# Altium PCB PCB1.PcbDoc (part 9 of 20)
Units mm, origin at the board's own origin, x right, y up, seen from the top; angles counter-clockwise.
Board outline 294.51 x 138.18 mm, 12 copper layers (Top Layer 1 _Signal, L2_GND, L3_Signals, L4_GND, L5_POWER, L6_Signals, L7_GND, L8_Signals, L9_GND, L10_POWER, L11_GND, Bottom Layer_Signals), stack 1.788 mm thick; 1254 components, 836 nets, 5699 pads, 2073 vias.
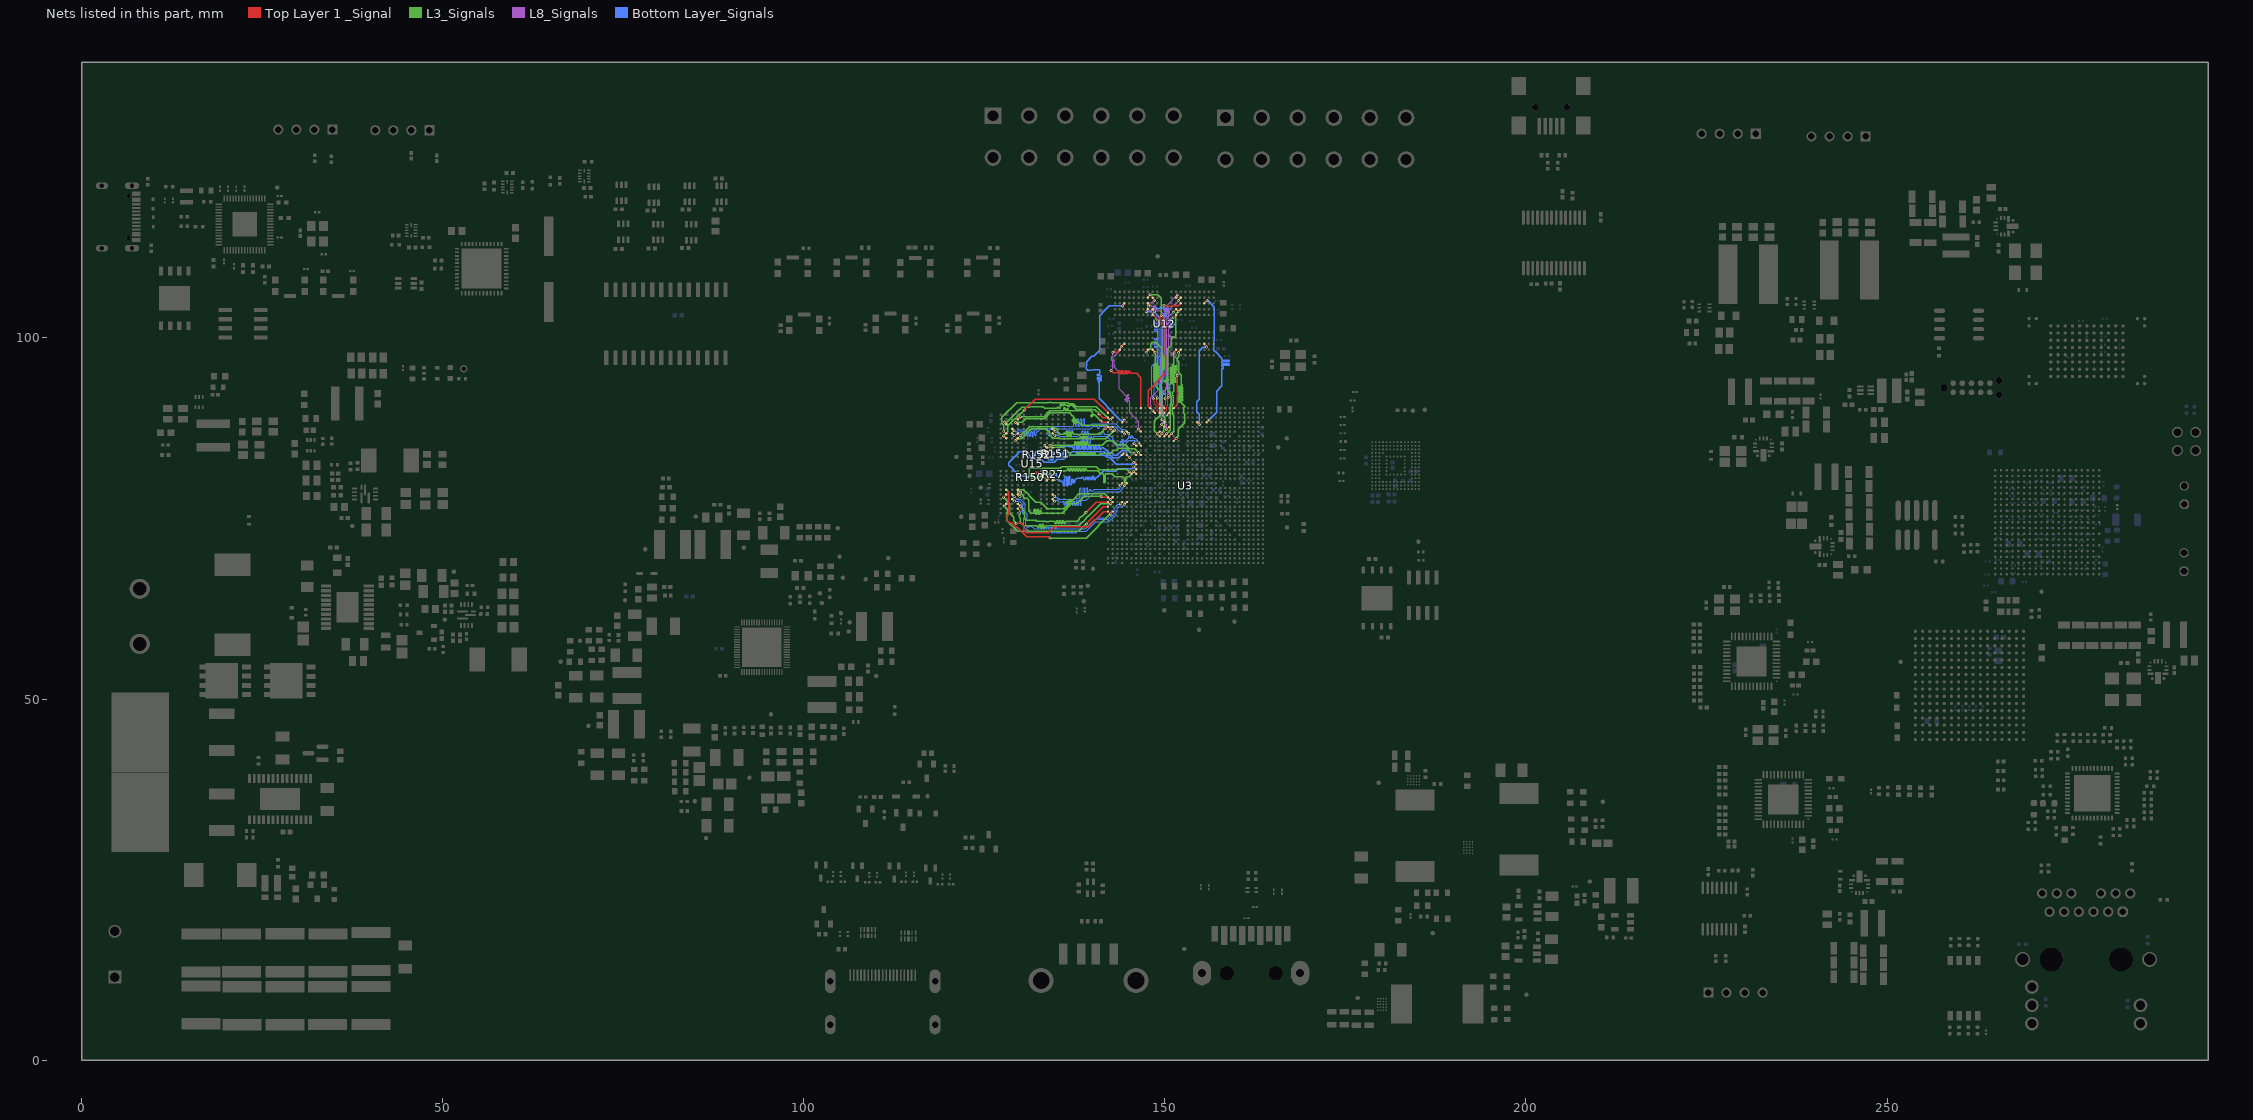
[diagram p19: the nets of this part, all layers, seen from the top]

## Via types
v1: diameter 0.4, hole 0.2, Top Layer 1 _Signal to Bottom Layer_Signals, 2009 vias
v2: diameter 0.508, hole 0.254, Top Layer 1 _Signal to Bottom Layer_Signals, 36 vias
v3: diameter 0.5, hole 0.2, Top Layer 1 _Signal to Bottom Layer_Signals, 12 vias
v4: diameter 1.27, hole 0.711, Top Layer 1 _Signal to Bottom Layer_Signals, 6 vias
v5: diameter 0.3, hole 0.2, Top Layer 1 _Signal to Bottom Layer_Signals, 5 vias
v6: diameter 0.254, hole 0.2, Top Layer 1 _Signal to Bottom Layer_Signals, 3 vias
v7: diameter 0.305, hole 0.2, Top Layer 1 _Signal to Bottom Layer_Signals, 1 vias
v8: diameter 0.254, hole 0.152, Top Layer 1 _Signal to Bottom Layer_Signals, 1 vias

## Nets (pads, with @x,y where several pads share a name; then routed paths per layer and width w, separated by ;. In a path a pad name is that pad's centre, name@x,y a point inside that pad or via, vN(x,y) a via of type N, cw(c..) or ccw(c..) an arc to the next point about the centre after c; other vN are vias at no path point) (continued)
DDR_CH0_DQ9_A: U3.AB1 U15.C11 | length 18.7
  Top Layer 1 _Signal w0.203: v1(127.74,76.71) 127.759,76.71 128.05,77.001 U15.C11@128.05,77.021 ; v1(139.147,74.236) 139.147,74.287 141.487,76.628 U3.AB1@142.129,76.628
  L3_Signals w0.179: v1(127.74,76.71) 128.196,76.254 128.196,74.639 129.636,73.199 138.11,73.199 v1(139.147,74.236)
DDR_CH0_DQ9_B: U3.C1 U15.Y11 | length 18.2
  Top Layer 1 _Signal w0.203: v1(127.779,88.35) 127.779,88.346 128.05,88.075 U15.Y11@128.05,88.071 ; v1(140.887,89.489) 141.398,88.978 U3.C1@142.129,88.978
  L3_Signals w0.179: v1(127.779,88.35) 128.114,88.35 129.922,90.157 129.955,90.157 130.213,90.415 131.322,90.415 131.411,90.504 133.062,90.504 133.336,90.23 135,90.23 135.061,90.23 135.09,90.259 135.09,90.379 135.295,90.379 135.295,90.244 135.499,90.244 135.499,90.794 135.704,90.794 135.704,90.595 135.909,90.595 135.909,90.794 136.114,90.794 136.114,90.648 136.318,90.648 136.318,90.699 136.523,90.699 136.523,90.481 136.728,90.481 136.728,90.648 136.861,90.648 137.204,90.648 137.703,90.149 139.865,90.149 139.942,90.071 140.305,90.071 v1(140.887,89.489)
DDR_CH0_DQ10_A: U3.AC1 U15.E11 | length 19.7
  Top Layer 1 _Signal w0.203: v1(127.658,77.928) U15.E11@128.05,78.321 ; v1(129.413,74.317) 130.09,74.317 130.432,73.975 130.432,73.413 130.8,73.045 133.863,73.045 134.668,73.85 139.403,73.85 141.514,75.961 142.113,75.961 U3.AC1@142.129,75.978
  L3_Signals w0.179: v1(127.658,77.928) 128.535,77.051 128.535,75.712 129.091,75.156 129.091,74.658 129.413,74.337 v1(129.413,74.317)
DDR_CH0_DQ10_B: U3.C2 U15.V11 | length 19.9
  Top Layer 1 _Signal w0.203: v1(127.688,87.075) 127.717,87.075 128.021,86.771 U15.V11@128.05,86.771 ; v1(142.47,88.679) 142.475,88.679 142.774,88.978 U3.C2@142.779,88.978
  L3_Signals w0.179: v1(127.688,87.075) 127.688,87.914 127.406,88.195 127.406,89.003 129.46,91.057 133.958,91.057 133.962,91.061 134.271,91.061 134.275,91.057 136.532,91.057 136.678,90.911 137.313,90.911 137.748,90.477 140.515,90.477 142.27,88.721 142.428,88.721 v1(142.47,88.679)
DDR_CH0_DQ11_A: U3.AC2 U15.F11 | length 21.7
  Top Layer 1 _Signal w0.203: U15.F11@128.05,78.971 128.41,78.61 128.41,75.571 128.196,75.357 128.196,74.662 128.432,74.426 128.78,74.426 129.027,74.178 129.027,74.157 129.383,73.802 129.551,73.802 130.901,72.452 133.914,72.452 134.043,72.323 v1(134.096,72.323) ; v1@142.439,75.637 v1(142.443,75.642) U3.AC2@142.779,75.978
  L3_Signals w0.179: v1(134.096,72.323) 134.124,72.295 139.097,72.295 v1(142.443,75.642)
DDR_CH0_DQ11_B: U3.B1 U15.U11 | length 18.3
  Top Layer 1 _Signal w0.203: v1(127.677,86.425) 127.711,86.425 128.016,86.121 U15.U11@128.05,86.121 ; v1(130.554,90.041) 132.045,91.532 140.225,91.532 U3.B1@142.129,89.628
  L3_Signals w0.179: v1(127.677,86.425) 128.247,86.995 128.247,87.834 130.017,89.604 130.117,89.604 v1(130.554,90.041)
DDR_CH0_DQ12_A: U3.Y1 U15.F9 | length 18.6
  Top Layer 1 _Signal w0.203: U15.F9@129.659,78.971 U15.F9@129.65,78.971 129.653,78.971 129.998,78.626 v1(130.001,78.626) ; v1(141.192,78.063) 141.245,78.063 141.381,77.928 U3.Y1@142.129,77.928
  L3_Signals w0.179: v1(130.001,78.626) 130.043,78.584 130.043,78.456 130.378,78.12 130.378,78.026 130.597,77.807 130.77,77.807 130.808,77.769 130.918,77.769 131.137,77.55 131.137,77.44 131.151,77.426 131.151,76.045 131.474,75.722 131.606,75.722 131.696,75.722 ccw(c131.696,75.901) 131.875,75.901 131.875,76.15 cw(c131.977,76.15) 132.08,76.15 132.08,75.701 ccw(c132.182,75.701) 132.284,75.701 132.284,76.15 cw(c132.387,76.15) 132.489,76.15 132.489,75.701 ccw(c132.592,75.701) 132.694,75.701 132.694,75.998 cw(c132.796,75.998) 132.899,75.998 132.899,75.901 ccw(c133.078,75.901) 133.078,75.722 133.996,75.722 134.413,75.722 134.417,75.726 134.727,75.726 134.731,75.722 135.766,75.722 137.062,77.017 137.784,77.017 138.831,78.063 v1(141.192,78.063)
DDR_CH0_DQ12_B: U3.F2 U15.U9 | length 18.3
  Top Layer 1 _Signal w0.203: v1@129.242,85.764 v1@129.268,85.764 ; v1@129.31,85.78 U15.U9@129.65,86.12 ; U15.U9@129.625,86.121 U15.U9@129.65,86.121 ; U3.F2@142.779,87.028 142.811,87.028 v1(143.061,87.278) v1@143.091,87.278
  L3_Signals w0.179: v1(129.31,85.779) 129.592,86.061 130.139,86.061 131.526,87.448 133.453,87.448 134.035,86.865 134.035,86.591 134.5,86.126 134.967,86.126 134.997,86.095 135.469,86.095 135.495,86.069 135.805,86.069 135.838,86.035 137.991,86.035 138.081,86.035 ccw(c138.081,86.215) 138.26,86.215 138.26,86.244 cw(c138.363,86.244) 138.465,86.244 138.465,86.112 ccw(c138.567,86.112) 138.67,86.112 138.67,86.312 cw(c138.772,86.312) 138.874,86.312 138.874,86.112 ccw(c138.977,86.112) 139.079,86.112 139.079,86.312 cw(c139.182,86.312) 139.284,86.312 139.284,86.215 ccw(c139.463,86.215) 139.463,86.035 141.113,86.035 141.818,86.035 v1(143.061,87.278)
DDR_CH0_DQ13_A: U3.Y2 U15.E9 | length 18.5
  Top Layer 1 _Signal w0.203: U15.E9@129.65,78.321 v1(129.924,78.046) ; v1(142.494,77.634) 142.494,77.638 142.779,77.923 U3.Y2@142.779,77.928
  L3_Signals w0.179: v1(129.924,78.046) 129.924,78.106 129.627,78.403 129.627,78.781 129.846,78.999 130.36,78.999 130.805,78.554 130.907,78.554 131.125,78.335 131.125,78.234 132.117,77.242 132.801,77.242 133.712,76.331 136.004,76.331 136.592,76.919 136.655,76.983 136.373,77.266 136.517,77.41 136.8,77.128 136.945,77.272 136.697,77.52 136.842,77.665 137.09,77.417 137.559,77.886 138.085,78.413 139.219,78.413 139.243,78.437 141.646,78.437 142.449,77.634 v1(142.494,77.634)
DDR_CH0_DQ13_B: U3.E1 U15.V9 | length 17
  Top Layer 1 _Signal w0.203: U15.V9@129.65,86.77 v1@129.985,86.435 ; v1(141.71,87.426) 141.747,87.464 141.884,87.464 142.098,87.678 U3.E1@142.129,87.678
  L3_Signals w0.179: v1(129.985,86.435) 131.261,87.711 134.429,87.711 134.659,87.48 134.969,87.48 135.188,87.261 135.188,86.968 135.478,86.677 135.968,86.677 136.058,86.677 ccw(c136.058,86.857) 136.237,86.857 136.237,86.88 cw(c136.34,86.88) 136.442,86.88 136.442,86.401 ccw(c136.545,86.401) 136.647,86.401 136.647,86.88 cw(c136.749,86.88) 136.852,86.88 136.852,86.401 ccw(c136.954,86.401) 137.056,86.401 137.056,86.88 cw(c137.159,86.88) 137.261,86.88 137.261,86.857 ccw(c137.44,86.857) 137.44,86.677 137.729,86.677 137.868,86.677 137.936,86.609 138.246,86.609 138.314,86.677 140.809,86.677 141.016,86.885 141.168,86.885 v1(141.71,87.426)
DDR_CH0_DQ14_A: U3.AA1 U15.C9 | length 17.9
  Top Layer 1 _Signal w0.203: U15.C9@129.65,77.021 129.958,76.712 v1(129.973,76.712) ; v1(139.107,75.856) 140.529,77.278 U3.AA1@142.129,77.278
  L3_Signals w0.179: v1(129.973,76.712) 130.015,76.67 130.015,76.534 130.359,76.19 130.359,76.182 130.553,75.987 130.553,75.527 130.613,75.468 130.613,75.158 130.553,75.099 130.553,75.016 130.79,74.779 132.09,74.779 132.275,74.594 133.557,74.594 133.587,74.565 133.896,74.565 133.926,74.594 134.309,74.594 134.603,74.594 cw(c134.603,74.415) 134.783,74.415 134.783,74.367 ccw(c134.885,74.367) 134.987,74.367 134.987,74.614 cw(c135.09,74.614) 135.192,74.614 135.192,74.367 ccw(c135.294,74.367) 135.397,74.367 135.397,74.614 cw(c135.499,74.614) 135.602,74.614 135.602,74.367 ccw(c135.704,74.367) 135.806,74.367 135.806,74.614 cw(c135.909,74.614) 136.011,74.614 136.011,74.403 ccw(c136.113,74.403) 136.216,74.403 136.216,74.415 cw(c136.395,74.415) 136.395,74.594 136.97,74.594 137.84,74.594 138.159,74.913 138.159,75.053 138.377,75.272 138.517,75.272 139.101,75.856 v1(139.107,75.856)
DDR_CH0_DQ14_B: U3.E2 U15.Y9 | length 17.4
  Top Layer 1 _Signal w0.203: v1(129.318,88.293) 129.355,88.256 129.425,88.256 129.61,88.071 U15.Y9@129.65,88.071 ; v1(142.484,87.411) 142.498,87.411 142.765,87.678 U3.E2@142.779,87.678
  L3_Signals w0.179: v1(129.318,88.293) 130.242,88.293 130.74,88.792 131.069,88.792 131.072,88.795 131.147,88.795 131.191,88.84 132.019,88.84 132.063,88.795 133.327,88.795 133.68,89.149 133.68,89.199 133.899,89.418 133.949,89.418 134.154,89.622 136.832,89.622 137.201,89.254 137.264,89.191 137.409,89.046 cw(c137.282,88.919) 137.409,88.792 137.207,88.59 ccw(c137.279,88.518) 137.207,88.446 ccw(c137.279,88.518) 137.352,88.446 137.626,88.72 cw(c137.698,88.647) 137.771,88.72 cw(c137.698,88.647) 137.771,88.575 137.496,88.301 ccw(c137.569,88.228) 137.496,88.156 ccw(c137.569,88.228) 137.641,88.156 137.843,88.358 cw(c137.97,88.231) 138.097,88.358 138.378,88.076 138.442,88.013 138.515,87.94 141.955,87.94 v1(142.484,87.411)
DDR_CH0_DQ15_A: U3.AA2 U15.B9 | length 18.7
  Top Layer 1 _Signal w0.203: U15.B9@129.65,76.371 v5(129.985,76.035) ; v1(142.483,77.009) 142.528,77.009 142.779,77.26 U3.AA2@142.779,77.278
  L3_Signals w0.179: v5(129.985,76.035) 129.985,75.587 129.866,75.468 129.866,75.158 129.953,75.071 129.953,74.471 130.434,73.99 131.714,73.99 132.199,73.99 cw(c132.199,73.81) 132.379,73.81 ccw(c132.481,73.81) 132.583,73.81 132.583,74.071 cw(c132.686,74.071) 132.788,74.071 132.788,73.75 ccw(c132.89,73.75) 132.993,73.75 132.993,74.095 cw(c133.095,74.095) 133.197,74.095 133.197,73.75 ccw(c133.3,73.75) 133.402,73.75 133.402,73.81 cw(c133.581,73.81) 133.581,73.99 133.671,73.99 138.063,73.99 138.598,74.525 138.687,74.525 138.906,74.744 138.906,74.832 139.353,75.28 139.363,75.28 141.092,77.009 v1(142.483,77.009)
DDR_CH0_DQ15_B: U3.D1 U15.AA9 | length 15.6
  Top Layer 1 _Signal w0.203: U15.AA9@129.65,88.721 129.656,88.721 129.99,89.055 v1(129.996,89.055) ; v1(141.149,88.492) 141.203,88.492 141.366,88.328 U3.D1@142.129,88.328
  L3_Signals w0.179: v1(129.996,89.055) 130.96,89.055 130.996,89.091 131.07,89.091 131.082,89.103 132.128,89.103 132.172,89.059 133.218,89.059 133.417,89.258 133.417,89.308 133.79,89.681 133.84,89.681 134.045,89.885 134.501,89.885 135.819,89.885 ccw(c135.819,90.065) 135.998,90.065 135.998,90.245 cw(c136.1,90.245) 136.203,90.245 136.203,89.988 ccw(c136.305,89.988) 136.408,89.988 136.408,90.116 cw(c136.51,90.116) 136.612,90.116 136.612,90.065 ccw(c136.792,90.065) 136.792,89.885 137.244,89.885 139.745,89.885 139.756,89.885 139.814,89.827 139.951,89.69 cw(c139.825,89.563) 139.951,89.436 139.788,89.272 ccw(c139.857,89.204) 139.788,89.135 ccw(c139.857,89.204) 139.925,89.135 140.089,89.298 cw(c140.216,89.172) 140.343,89.298 140.543,89.098 140.606,89.035 v1(141.149,88.492)
DDR_CH0_DQS0_A_N: U3.U4 U15.E3 | length 18.3
  Top Layer 1 _Signal w0.161: U15.E3@134.45,78.321 134.501,78.321 v1(134.759,78.063) ; v1(143.813,79.606) 143.813,79.612 U3.U4@144.079,79.878
  Bottom Layer_Signals w0.161: v1(134.759,78.063) 134.793,78.063 135,77.856 135.208,77.856 135.408,77.657 137.289,77.657 137.46,77.828 138.002,77.828 138.083,77.828 ccw(c138.083,77.989) 138.244,77.989 138.244,79.106 cw(c138.35,79.106) 138.456,79.106 138.456,77.934 ccw(c138.562,77.934) 138.668,77.934 138.668,79.106 cw(c138.774,79.106) 138.88,79.106 138.88,78.029 ccw(c138.986,78.029) 139.092,78.029 139.092,79.106 cw(c139.198,79.106) 139.304,79.106 139.304,78.454 ccw(c139.41,78.454) 139.516,78.454 139.516,78.893 cw(c139.622,78.893) 139.728,78.893 ccw(c139.889,78.976) 140.016,78.848 140.175,79.006 140.217,79.048 143.625,79.048 143.847,79.27 143.847,79.573 v1(143.813,79.606)
DDR_CH0_DQS0_A_P: U3.U5 U15.D3 | length 18.7
  Top Layer 1 _Signal w0.161: U15.D3@134.45,77.671 v1(134.731,77.39) ; v1(144.432,79.581) U3.U5@144.729,79.878
  Bottom Layer_Signals w0.161: v1(134.731,77.39) 134.792,77.39 134.945,77.542 135.078,77.542 135.102,77.519 135.278,77.343 135.894,77.343 cw(c135.894,77.182) 136.055,77.182 136.055,76.906 ccw(c136.147,76.906) 136.238,76.906 136.238,77.251 cw(c136.33,77.251) 136.422,77.251 136.422,76.906 ccw(c136.513,76.906) 136.605,76.906 136.605,77.251 cw(c136.697,77.251) 136.788,77.251 136.788,76.906 ccw(c136.88,76.906) 136.972,76.906 136.972,77.251 cw(c137.064,77.251) 137.155,77.251 137.155,76.906 ccw(c137.247,76.906) 137.339,76.906 137.339,77.255 cw(c137.43,77.255) 137.522,77.255 137.522,76.906 ccw(c137.614,76.906) 137.705,76.906 137.705,77.427 cw(c137.797,77.427) 137.889,77.427 137.889,76.906 ccw(c137.981,76.906) 138.072,76.906 138.072,77.423 cw(c138.164,77.423) 138.256,77.423 138.256,76.906 ccw(c138.347,76.906) 138.439,76.906 138.439,77.353 cw(c138.6,77.353) 138.6,77.515 139.068,77.515 139.127,77.515 140.347,78.734 143.754,78.734 144.161,79.14 144.161,79.248 144.432,79.52 v1(144.432,79.581)
DDR_CH0_DQS0_B_N: U3.J7 U15.V3 | length 21.3
  Top Layer 1 _Signal w0.161: U15.V3@134.501,86.771 U15.V3@134.45,86.771 134.476,86.771 134.747,86.499 v1(134.772,86.499) ; v1(145.739,85.349) 145.749,85.349 146.02,85.078 U3.J7@146.029,85.078 146.011,85.078 U3.J7@146.011,85.087
  Bottom Layer_Signals w0.161: v1(134.772,86.499) 134.837,86.499 134.932,86.595 134.979,86.595 135.01,86.625 135.148,86.625 135.4,86.373 137.742,86.373 137.81,86.304 137.983,86.304 138.251,86.304 cw(c138.251,86.143) 138.412,86.143 138.412,85.513 ccw(c138.505,85.513) 138.599,85.513 138.599,86.28 cw(c138.692,86.28) 138.785,86.28 138.785,85.513 ccw(c138.879,85.513) 138.972,85.513 138.972,86.293 cw(c139.065,86.293) 139.159,86.293 139.159,85.513 ccw(c139.252,85.513) 139.345,85.513 139.345,86.279 cw(c139.439,86.279) 139.532,86.279 139.532,85.513 ccw(c139.625,85.513) 139.719,85.513 139.719,86.279 cw(c139.812,86.279) 139.905,86.279 139.905,86.073 ccw(c139.999,86.073) 140.092,86.073 140.092,86.211 cw(c140.253,86.211) 140.253,86.373 140.809,86.373 142.011,86.373 142.137,86.246 142.137,86.163 143.378,84.922 143.439,84.922 143.623,84.738 144.028,84.738 145.093,85.803 145.731,85.803 145.838,85.697 145.838,85.512 145.739,85.414 v1(145.739,85.349)
DDR_CH0_DQS0_B_P: U3.J8 U15.W3 | length 21.4
  Top Layer 1 _Signal w0.161: U15.W3@134.45,87.421 134.764,87.107 v1(134.814,87.107) ; v1(146.403,85.471) 146.449,85.425 146.449,85.352 146.679,85.121 U3.J8@146.679,85.078
  Bottom Layer_Signals w0.161: v1@134.731,86.994 134.861,86.994 134.915,86.939 135.278,86.939 135.53,86.686 136.108,86.686 136.189,86.686 ccw(c136.189,86.848) 136.35,86.848 136.35,87.086 cw(c136.444,87.086) 136.537,87.086 136.537,86.78 ccw(c136.63,86.78) 136.724,86.78 136.724,87.074 cw(c136.817,87.074) 136.91,87.074 136.91,86.78 ccw(c137.004,86.78) 137.097,86.78 137.097,87.074 cw(c137.19,87.074) 137.284,87.074 137.284,86.848 ccw(c137.445,86.848) 137.445,86.686 137.762,86.686 137.872,86.686 137.94,86.618 138.242,86.618 138.275,86.651 138.31,86.686 138.356,86.686 ccw(c138.356,86.848) 138.517,86.848 138.517,87.005 cw(c138.607,87.005) 138.696,87.005 138.696,86.776 ccw(c138.786,86.776) 138.875,86.776 138.875,87.005 cw(c138.965,87.005) 139.054,87.005 139.054,86.79 ccw(c139.144,86.79) 139.233,86.79 139.233,87.005 cw(c139.323,87.005) 139.412,87.005 139.412,86.848 ccw(c139.574,86.848) 139.574,86.686 140.689,86.686 141.101,86.686 141.182,86.686 ccw(c141.182,86.848) 141.343,86.848 141.343,86.997 cw(c141.436,86.997) 141.53,86.997 141.53,86.848 ccw(c141.691,86.848) 141.691,86.686 142.09,86.686 142.141,86.686 142.751,86.076 142.751,85.98 143.363,85.369 143.436,85.369 143.753,85.052 143.898,85.052 143.955,85.109 ccw(c143.841,85.223) 143.955,85.337 143.81,85.482 cw(c143.876,85.548) 143.81,85.614 cw(c143.876,85.548) 143.942,85.614 144.135,85.421 ccw(c144.201,85.487) 144.267,85.421 ccw(c144.201,85.487) 144.267,85.553 144.074,85.746 cw(c144.14,85.812) 144.074,85.878 cw(c144.14,85.812) 144.206,85.878 144.351,85.733 ccw(c144.465,85.847) 144.579,85.733 144.874,86.028 144.877,86.031 144.957,86.112 ccw(c144.843,86.225) 145.004,86.224 145.004,86.292 cw(c145.097,86.292) 145.191,86.292 145.191,86.21 ccw(c145.284,86.21) 145.377,86.21 145.377,86.292 cw(c145.471,86.292) 145.564,86.292 145.564,86.278 ccw(c145.725,86.278) 145.725,86.117 145.931,86.117 146.032,86.016 146.032,85.946 146.151,85.827 146.151,85.743 146.403,85.491 v1(146.403,85.471)
DDR_CH0_DQS1_A_N: U3.AA4 U15.E10 | length 25.2
  Top Layer 1 _Signal w0.161: U15.E10@128.85,78.321 v1(129.124,78.046) ; v1(143.819,77.018) U3.AA4@144.079,77.278
  Bottom Layer_Signals w0.161: v1(129.124,78.046) 129.489,77.682 129.962,77.682 130.663,76.981 130.663,75.848 130.917,75.594 130.917,75.032 130.749,74.864 130.749,73.976 130.919,73.807 131.052,73.807 131.199,73.953 131.501,73.953 131.89,73.564 132.92,73.564 133,73.564 133,73.777 133.187,73.777 133.187,73.564 133.374,73.564 133.374,73.777 133.56,73.777 133.56,73.564 133.747,73.564 133.747,73.777 133.934,73.777 133.934,73.564 134.121,73.564 134.121,73.777 134.307,73.777 134.307,73.564 134.494,73.564 134.494,73.777 134.681,73.777 134.681,73.564 134.867,73.564 134.867,73.777 135.054,73.777 135.054,73.564 135.507,73.564 138.99,73.564 139.239,73.813 139.56,74.134 139.542,74.152 139.674,74.284 139.692,74.266 139.824,74.398 139.806,74.416 139.938,74.548 139.956,74.53 140.158,74.732 140.298,74.872 140.569,74.872 140.649,74.872 140.649,75.099 140.836,75.099 140.836,74.872 141.023,74.872 141.023,75.099 141.209,75.099 141.209,74.872 141.396,74.872 141.396,75.099 141.583,75.099 141.583,74.872 141.878,74.872 142.106,74.872 142.42,75.185 142.512,75.277 142.594,75.277 142.967,75.65 142.967,76.441 143.482,76.956 143.606,76.956 143.621,76.972 143.774,76.972 v1(143.819,77.018)
DDR_CH0_DQS1_A_P: U3.AA5 U15.D10 | length 25.9
  Top Layer 1 _Signal w0.161: U15.D10@128.85,77.671 129.119,77.401 v1(129.18,77.401) ; v1(144.444,76.993) U3.AA5@144.729,77.278
  Bottom Layer_Signals w0.161: v1(129.18,77.401) 129.213,77.368 129.832,77.368 130.35,76.851 130.35,75.718 130.604,75.464 130.604,75.162 130.435,74.994 130.435,73.846 130.789,73.493 130.93,73.493 131.199,73.224 131.541,73.224 131.567,73.25 134.012,73.25 134.279,73.25 134.279,73.039 134.466,73.039 134.466,73.25 134.652,73.25 134.652,73.039 134.839,73.039 134.839,73.25 135.026,73.25 135.026,73.039 135.212,73.039 135.212,73.25 135.399,73.25 135.399,73.039 135.586,73.039 135.586,73.25 135.773,73.25 135.773,73.039 135.959,73.039 135.959,73.25 136.146,73.25 136.146,73.039 136.333,73.039 136.333,73.25 136.519,73.25 136.519,73.039 136.706,73.039 136.706,73.25 136.893,73.25 136.893,73.039 137.079,73.039 137.079,73.25 137.266,73.25 137.266,73.039 137.453,73.039 137.453,73.25 137.639,73.25 137.639,73.039 137.826,73.039 137.826,73.25 138.107,73.25 139.12,73.25 140.428,74.558 142.236,74.558 142.642,74.964 142.724,74.964 143.281,75.52 143.281,76.107 143.375,76.202 143.399,76.202 143.399,76.429 143.612,76.643 144.084,76.643 144.434,76.993 v1(144.444,76.993)
DDR_CH0_DQS1_B_N: U3.F4 U15.V10 | length 24.6
  Top Layer 1 _Signal w0.161: U15.V10@128.85,86.771 v1(129.132,86.488) ; U3.F4@144.079,87.028 144.079,87.017 144.405,86.691 v1(144.405,86.68)
  Bottom Layer_Signals w0.161: v1(129.132,86.488) 129.171,86.488 129.346,86.663 129.596,86.663 129.814,86.882 129.937,87.005 130.34,87.005 cw(c130.34,86.843) 130.502,86.843 130.502,86.501 ccw(c130.595,86.501) 130.688,86.501 130.688,86.911 cw(c130.782,86.911) 130.875,86.911 130.875,86.501 ccw(c130.968,86.501) 131.062,86.501 131.062,86.911 cw(c131.155,86.911) 131.248,86.911 131.248,86.501 ccw(c131.342,86.501) 131.435,86.501 131.435,86.911 cw(c131.528,86.911) 131.622,86.911 131.622,86.39 ccw(c131.715,86.39) 131.808,86.39 131.808,86.911 cw(c131.902,86.911) 131.995,86.911 131.995,86.595 ccw(c132.089,86.595) 132.182,86.595 132.182,86.843 cw(c132.343,86.843) 132.343,87.005 132.409,87.005 132.813,87.409 132.851,87.447 133.076,87.447 133.69,87.447 cw(c133.69,87.286) 133.851,87.286 133.851,86.543 ccw(c133.94,86.543) 134.029,86.543 134.029,87.286 cw(c134.19,87.286) 134.19,87.447 134.639,87.447 134.663,87.471 134.965,87.471 134.989,87.447 135.319,87.447 136.577,87.447 136.612,87.413 137.174,87.413 137.209,87.447 139.764,87.447 140.107,87.791 140.287,87.791 140.554,87.791 ; 140.554,87.791 cw(c140.554,87.629) 140.716,87.629 140.716,87.568 ccw(c140.809,87.568) 140.902,87.568 140.902,87.629 cw(c141.064,87.629) 141.064,87.791 ; 141.064,87.791 142.07,87.791 143.064,87.791 143.838,87.017 144.25,87.017 144.359,86.908 144.359,86.726 v1(144.405,86.68)
DDR_CH0_DQS1_B_P: U3.F5 U15.W10 | length 25
  Top Layer 1 _Signal w0.161: U15.W10@128.85,87.421 v1(129.118,87.152) ; U3.F5@144.729,87.009 U3.F5@144.729,87.028 144.736,87.028 v1(145.003,86.76)
  Bottom Layer_Signals w0.161: v1(129.118,87.152) 129.157,87.152 129.332,86.977 129.466,86.977 129.807,87.318 132.279,87.318 132.721,87.761 134.509,87.761 134.533,87.785 135.095,87.785 135.119,87.761 136.707,87.761 136.742,87.726 137.044,87.726 137.079,87.761 137.175,87.761 137.255,87.761 ccw(c137.255,87.922) 137.417,87.922 137.417,88.651 cw(c137.523,88.651) 137.629,88.651 137.629,87.867 ccw(c137.735,87.867) 137.841,87.867 137.841,88.651 cw(c137.947,88.651) 138.053,88.651 138.053,87.867 ccw(c138.159,87.867) 138.265,87.867 138.265,88.651 cw(c138.371,88.651) 138.477,88.651 138.477,87.867 ccw(c138.583,87.867) 138.689,87.867 138.689,88.651 cw(c138.795,88.651) 138.901,88.651 138.901,87.922 ccw(c139.063,87.922) 139.063,87.761 139.634,87.761 139.695,87.822 139.977,88.104 143.193,88.104 143.968,87.33 144.38,87.33 144.95,86.76 v1(145.003,86.76)
DDR_CH0_LP4/4X_CKE0/LP5_CS0_A: R27.1 U3.P7 | length 21.2
  Top Layer 1 _Signal w0.203: v1(145.707,82.128) 145.718,82.128 146.018,81.828 U3.P7@146.029,81.828 U3.P7@146.026,81.828
  Bottom Layer_Signals w0.203: R27.1@134.872,81.112 134.872,81.087 135.232,80.726 135.232,80.414 135.235,80.412 135.488,80.158 135.732,80.158 cw(c135.732,79.955) 135.935,79.955 135.935,79.669 ccw(c136.049,79.669) 136.164,79.669 136.164,80.678 cw(c136.278,80.678) 136.392,80.678 136.392,79.669 ccw(c136.507,79.669) 136.621,79.669 136.621,80.726 cw(c136.735,80.726) 136.849,80.726 136.849,79.786 ccw(c136.964,79.786) 137.078,79.786 137.078,80.319 cw(c137.192,80.319) 137.307,80.319 137.307,80.029 ccw(c137.421,80.029) 137.535,80.029 137.535,80.199 cw(c137.738,80.198) 137.592,80.339 137.694,80.44 137.855,80.602 138.08,80.602 138.441,80.602 138.55,80.711 138.591,80.711 cw(c138.591,80.508) 138.794,80.508 138.794,80.5 ccw(c138.908,80.5) 139.022,80.5 139.022,80.595 cw(c139.137,80.595) 139.251,80.595 139.251,80.5 ccw(c139.365,80.5) 139.48,80.5 139.48,80.616 cw(c139.594,80.616) 139.708,80.616 139.708,80.5 ccw(c139.823,80.5) 139.937,80.5 139.937,80.749 cw(c140.051,80.749) 140.165,80.749 140.165,80.5 ccw(c140.28,80.5) 140.394,80.5 140.394,80.508 cw(c140.597,80.508) 140.597,80.711 140.642,80.711 140.699,80.768 141.51,81.579 142.014,81.579 142.083,81.509 143.193,81.509 143.548,81.864 145.443,81.864 v1(145.707,82.128)
DDR_CH0_LP4/4X_CKE0/LP5_CS0_B: R151.1 U3.L5 | length 21.1
  Top Layer 1 _Signal w0.203: U3.L5@144.729,83.778 144.741,83.778 145.066,83.453 v1(145.077,83.453)
  Bottom Layer_Signals w0.203: R151.1@135.242,83.991 135.304,84.054 135.304,84.67 135.607,84.972 135.95,84.972 136,85.023 136.691,85.023 136.785,84.929 137.115,84.929 cw(c137.115,84.726) 137.318,84.726 137.318,84.664 ccw(c137.432,84.664) 137.547,84.664 137.547,85.042 cw(c137.661,85.042) 137.775,85.042 137.775,84.664 ccw(c137.89,84.664) 138.004,84.664 138.004,85.042 cw(c138.118,85.042) 138.233,85.042 138.233,84.664 ccw(c138.347,84.664) 138.461,84.664 138.461,85.039 cw(c138.575,85.039) 138.69,85.039 138.69,84.664 ccw(c138.804,84.664) 138.918,84.664 138.918,85.039 cw(c139.033,85.039) 139.147,85.039 139.147,84.664 ccw(c139.261,84.664) 139.376,84.664 139.376,85.039 cw(c139.49,85.039) 139.604,85.039 139.604,84.664 ccw(c139.718,84.664) 139.833,84.664 139.833,85.042 cw(c139.947,85.042) 140.061,85.042 140.061,84.664 ccw(c140.176,84.664) 140.29,84.664 140.29,85.042 cw(c140.404,85.042) 140.519,85.042 140.519,84.664 ccw(c140.633,84.664) 140.747,84.664 140.747,85.042 cw(c140.861,85.042) 140.976,85.042 140.976,84.664 ccw(c141.09,84.664) 141.204,84.664 cw(c141.4,84.609) 141.543,84.753 141.617,84.68 141.719,84.578 142.229,84.068 142.616,84.068 142.963,83.72 143.371,83.72 144.113,84.462 144.52,84.462 144.752,84.23 144.752,83.831 145.077,83.506 v1(145.077,83.453)
DDR_CH0_LP4/4X_CKE0_A: R27.2 U15.J4 | length 1.5
  Top Layer 1 _Signal w0.254: v1@133.301,81.27 v1(133.304,81.267) U15.J4@133.65,80.921
  Bottom Layer_Signals w0.254: v1(133.304,81.267) 133.344,81.267 133.498,81.112 R27.2@134.222,81.112
DDR_CH0_LP4/4X_CKE0_B: R151.2 U15.P4 | length 1.2
  Top Layer 1 _Signal w0.203: U15.P4@133.65,84.171 133.69,84.171 133.834,84.315 133.989,84.315 v1(134.027,84.353)
  Bottom Layer_Signals w0.203: v1(134.027,84.353) 134.064,84.315 134.293,84.315 134.592,84.016 R151.2@134.592,83.991
DDR_CH0_LP4/4X_CKE1/LP5_CS1_A: R150.1 U3.N7 | length 24
  Top Layer 1 _Signal w0.203: v1(145.717,82.791) U3.N7@146.029,82.478
  Bottom Layer_Signals w0.191: 135.174,83.195 135.18,83.202 135.97,83.202 136.048,83.28
  Bottom Layer_Signals w0.203: R150.1@131.036,80.709 130.984,80.761 130.785,80.761 130.711,80.836 129.791,80.836 129.452,81.175 129.452,81.344 128.662,82.134 128.604,82.134 128.378,82.359 128.378,82.743 129.612,83.977 129.612,83.983 129.87,84.241 130.925,84.241 131.15,84.015 131.15,83.752 131.662,83.24 132.03,83.24 132.039,83.232 132.404,83.232 132.429,83.207 132.897,83.207 133.303,82.801 134.69,82.801 135.085,83.195 135.174,83.195 ; 136.048,83.28 136.472,83.704 136.791,83.704 136.848,83.761 141.559,83.761 141.616,83.704 141.78,83.704 141.991,83.494 142.302,83.494 143.056,82.74 143.056,82.721 143.237,82.539 145.465,82.539 v1(145.717,82.791)
DDR_CH0_LP4/4X_CKE1/LP5_CS1_B: R152.1 U3.L4 | length 17.6
  Top Layer 1 _Signal w0.203: U3.L4@144.079,83.778 144.079,83.801 144.355,84.077 v1(144.36,84.077)
  Bottom Layer_Signals w0.203: R152.1@132.608,83.806 132.608,83.831 132.682,83.904 132.769,83.904 132.801,83.936 132.969,83.936 133.095,83.811 133.12,83.811 133.399,83.531 133.468,83.531 ccw(c133.468,83.735) 133.671,83.735 133.671,83.861 cw(c133.778,83.861) 133.885,83.861 133.885,83.194 ccw(c133.991,83.194) 134.098,83.194 134.098,83.528 cw(c134.205,83.528) 134.311,83.528 134.311,83.194 ccw(c134.418,83.194) 134.525,83.194 134.525,83.279 cw(c134.728,83.279) 134.728,83.482 135.256,83.482 135.259,83.485 135.331,83.557 135.388,83.5 135.55,83.662 135.729,83.482 135.891,83.644 135.602,83.933 135.764,84.094 136.11,83.748 136.272,83.91 135.953,84.228 136.13,84.405 136.365,84.405 136.373,84.405 136.69,84.087 137.009,84.087 137.184,84.263 140.21,84.263 141.628,84.263 ; 141.687,84.203 141.628,84.263 ; v1(144.36,84.077) 144.307,84.077 144.209,83.979 144.154,83.979 143.609,83.433 142.768,83.433 142.421,83.781 142.11,83.781 141.628,84.263
DDR_CH0_LP4/4X_CKE1_A: R150.2 U15.J5 | length 1.8
  Top Layer 1 _Signal w0.203: v1(131.994,81.253) 132.135,81.394 132.376,81.394 U15.J5@132.85,80.921
  Bottom Layer_Signals w0.203: R150.2@131.686,80.709 131.7,80.723 131.7,81.036 131.879,81.216 131.956,81.216 v1(131.994,81.253)
DDR_CH0_LP4/4X_CKE1_B: R152.2 U15.P5 | length 2.2
  Top Layer 1 _Signal w0.203: U15.P5@132.85,84.171 132.878,84.199 132.918,84.199 133.132,84.413 133.196,84.413 v1(133.233,84.451)
  Bottom Layer_Signals w0.203: R152.2@131.958,83.806 132.032,83.879 132.032,84.102 132.273,84.343 132.665,84.343 132.736,84.413 133.196,84.413 v1(133.233,84.451)
DDR_CH0_LP4/4X_CS0_A: U3.R6 U15.H4 | length 20.9
  Top Layer 1 _Signal w0.203: U15.H4@133.65,80.271 v1(133.972,80.592) ; v1(145.082,81.451) 145.094,81.451 145.367,81.178 U3.R6@145.379,81.178
  L3_Signals w0.179: v1(133.972,80.592) 133.934,80.555 133.422,80.555 133.128,80.555 cw(c133.128,80.734) 132.949,80.734 132.949,81.014 ccw(c132.846,81.014) 132.744,81.014 132.744,80.632 cw(c132.642,80.632) 132.539,80.632 132.539,81.014 ccw(c132.437,81.014) 132.335,81.014 132.335,80.734 cw(c132.155,80.734) 132.155,80.555 131.801,80.555 131.642,80.555 131.213,80.983 131.213,81.868 131.318,81.973 135.496,81.973 135.7,82.176 140.523,82.176 140.933,81.767 143.246,81.767 143.31,81.83 144.703,81.83 v1(145.082,81.451)
DDR_CH0_LP4/4X_CS0_B: U3.L7 U15.R4 | length 18.4
  Top Layer 1 _Signal w0.203: v1(133.372,85.098) U15.R4@133.65,84.821 ; v1(145.723,84.059) 146.004,83.778 U3.L7@146.029,83.778
  L3_Signals w0.179: v1(133.372,85.098) 133.71,84.76 134.641,84.76 134.764,84.883 135.535,84.883 ; 135.536,84.884 135.93,84.884 136.476,84.338 136.476,84.318 136.695,84.099 136.714,84.099 137.028,83.785 137.45,83.785 137.54,83.785 ccw(c137.54,83.965) 137.719,83.965 137.719,84.032 cw(c137.821,84.032) 137.924,84.032 137.924,83.862 ccw(c138.026,83.862) 138.128,83.862 138.128,84.032 cw(c138.231,84.032) 138.333,84.032 138.333,83.862 ccw(c138.435,83.862) 138.538,83.862 138.538,84.032 cw(c138.64,84.032) 138.742,84.032 138.742,83.862 ccw(c138.845,83.862) 138.947,83.862 138.947,84.032 cw(c139.05,84.032) 139.152,84.032 139.152,83.862 ccw(c139.254,83.862) 139.357,83.862 139.357,84.032 cw(c139.459,84.032) 139.561,84.032 139.561,83.862 ccw(c139.664,83.862) 139.766,83.862 139.766,84.032 cw(c139.868,84.032) 139.971,84.032 139.971,83.862 ccw(c140.073,83.862) 140.176,83.862 140.176,84.032 cw(c140.278,84.032) 140.38,84.032 140.38,83.965 ccw(c140.56,83.965) 140.56,83.785 140.866,83.785 141.042,83.962 142.417,83.962 142.934,84.479 143.288,84.479 143.523,84.714 144.624,84.714 145.248,84.09 145.693,84.09 v1(145.723,84.059)
DDR_CH0_LP4/4X_CS1_A: U3.R7 U15.H3 | length 21.9
  Top Layer 1 _Signal w0.203: U15.H3@134.45,80.271 134.478,80.299 134.661,80.299 134.752,80.39 v1(134.805,80.39) ; v1@145.693,81.488 v1(145.693,81.514) U3.R7@146.029,81.178 U3.R7@146.003,81.178
  L3_Signals w0.179: v1(134.805,80.39) 134.324,80.871 134.324,81.051 134.035,81.34 134.035,81.489 134.14,81.594 136.208,81.594 136.298,81.594 ccw(c136.298,81.773) 136.477,81.773 136.477,81.811 cw(c136.58,81.811) 136.682,81.811 136.682,81.671 ccw(c136.784,81.671) 136.887,81.671 136.887,81.811 cw(c136.989,81.811) 137.091,81.811 137.091,81.671 ccw(c137.194,81.671) 137.296,81.671 137.296,81.811 cw(c137.398,81.811) 137.501,81.811 137.501,81.671 ccw(c137.603,81.671) 137.705,81.671 137.705,81.811 cw(c137.808,81.811) 137.91,81.811 137.91,81.671 ccw(c138.013,81.671) 138.115,81.671 138.115,81.811 cw(c138.217,81.811) 138.32,81.811 138.32,81.671 ccw(c138.422,81.671) 138.524,81.671 138.524,81.811 cw(c138.627,81.811) 138.729,81.811 138.729,81.671 ccw(c138.831,81.671) 138.934,81.671 138.934,81.811 cw(c139.036,81.811) 139.139,81.811 139.139,81.773 ccw(c139.318,81.773) 139.318,81.594 139.643,81.594 140.733,81.594 141.033,81.294 141.117,81.21 141.328,81.21 cw(c141.328,81.031) 141.507,81.031 141.507,80.042 ccw(c141.609,80.042) 141.712,80.042 141.712,81.031 cw(c141.891,81.031) 141.891,81.21 142.615,81.21 142.782,81.043 143.072,80.753 143.473,80.753 144.177,80.753 cw(c144.177,80.574) 144.356,80.574 144.356,80.057 ccw(c144.458,80.057) 144.561,80.057 144.561,80.574 cw(c144.74,80.574) 144.74,80.753 145.039,80.753 145.389,81.103 145.429,81.143 145.429,81.19 145.693,81.454 v1(145.693,81.514)
DDR_CH0_LP4/4X_CS1_B: U3.L8 U15.R3 | length 18.5
  Top Layer 1 _Signal w0.203: v1(134.097,85.134) 134.41,84.821 U15.R3@134.45,84.821 ; v1(146.348,84.11) U3.L8@146.679,83.778
  L3_Signals w0.179: v1(134.097,85.134) 134.122,85.109 134.618,85.109 134.655,85.146 135.426,85.146 ; 135.427,85.147 137.224,85.147 137.313,85.147 ccw(c137.313,85.327) 137.493,85.327 137.493,85.553 cw(c137.595,85.553) 137.697,85.553 137.697,85.224 ccw(c137.8,85.224) 137.902,85.224 137.902,85.553 cw(c138.005,85.553) 138.107,85.553 138.107,85.224 ccw(c138.209,85.224) 138.312,85.224 138.312,85.553 cw(c138.414,85.553) 138.516,85.553 138.516,85.224 ccw(c138.619,85.224) 138.721,85.224 138.721,85.553 cw(c138.823,85.553) 138.926,85.553 138.926,85.224 ccw(c139.028,85.224) 139.131,85.224 139.131,85.553 cw(c139.233,85.553) 139.335,85.553 139.335,85.327 ccw(c139.515,85.327) 139.515,85.147 140.988,85.147 141.361,85.147 141.951,85.737 142.799,85.737 143.352,85.184 144.525,85.184 145.078,84.631 145.827,84.631 v1(146.348,84.11)
DDR_CH1_A0_C: U3.G12 U12.H2 | length 22.6
  Top Layer 1 _Signal w0.203: v1(147.424,98.015) 147.462,98.053 147.462,98.157 147.654,98.349 U12.H2@147.654,98.389 ; U3.G12@149.279,86.378 149.61,86.708 149.61,86.72 v1(149.604,86.726)
  L3_Signals w0.179: v1(147.424,98.015) 147.445,98.015 148.023,98.593 148.023,99.186 148.227,99.39 148.751,99.39 149.587,98.554 149.587,97.654 149.587,97.564 150.152,97.564 150.152,97.359 149.562,97.359 149.562,97.154 150.152,97.154 150.152,96.95 149.562,96.95 149.562,96.745 150.152,96.745 150.152,96.54 149.562,96.54 149.562,96.336 150.152,96.336 150.152,96.131 149.562,96.131 149.562,95.926 150.152,95.926 150.152,95.721 149.562,95.721 149.562,95.517 149.629,95.517 149.629,95.312 149.587,95.312 149.587,94.057 149.587,93.654 149.506,93.573 149.506,93.263 149.587,93.181 149.587,89.355 149.988,88.954 149.988,88.216 149.973,88.2 149.973,87.596 149.875,87.499 149.875,87.149 149.647,86.92 149.647,86.768 v1(149.604,86.726)
DDR_CH1_A0_D: U3.H15 U12.R2 | length 22.5
  Top Layer 1 _Signal w0.203: U3.H15@151.229,85.728 151.229,85.76 151.545,86.076 v1(151.554,86.076) ; v1(151.89,97.962) 151.928,97.999 151.928,98.072 152.204,98.349 U12.R2@152.204,98.389
  L3_Signals w0.179: v1(151.554,86.076) 151.554,86.117 151.866,86.428 151.866,87.358 152.783,88.275 152.783,89.425 152.627,89.58 152.627,90.326 152.783,90.481 152.783,90.57 152.368,90.984 152.279,91.074 151.773,91.074 151.773,91.279 152.48,91.279 152.48,91.483 151.773,91.483 151.773,91.688 152.48,91.688 152.48,91.893 151.773,91.893 151.773,92.097 152.48,92.097 152.48,92.302 151.773,92.302 151.773,92.507 152.48,92.507 152.48,92.712 151.773,92.712 151.773,92.916 152.48,92.916 152.48,93.121 151.773,93.121 151.773,93.326 152.424,93.326 152.424,93.531 152.255,93.531 152.255,94.819 151.89,95.184 151.89,96.722 151.706,96.906 151.706,97.215 151.89,97.399 v1(151.89,97.962)
DDR_CH1_A1_C: U3.F12 U12.J2 | length 21.3
  Top Layer 1 _Signal w0.205: U12.J2@148.304,98.389 148.304,98.372 148.639,98.038 v1(148.639,98.021) ; v1(148.986,86.711) 148.993,86.711 149.279,86.997 U3.F12@149.279,87.028
  L3_Signals w0.179: v1(148.639,98.021) 148.639,97.093 148.639,96.487 149.021,96.487 149.021,96.283 148.483,96.283 148.483,96.078 149.201,96.078 149.201,95.873 148.483,95.873 148.483,95.669 149.201,95.669 149.201,95.464 148.483,95.464 148.483,95.259 149.201,95.259 149.201,95.054 148.483,95.054 148.483,94.85 149.201,94.85 149.201,94.645 148.483,94.645 148.483,94.44 149.201,94.44 149.201,94.235 148.483,94.235 148.483,94.031 148.639,94.031 148.639,93.941 148.639,93.404 149.319,92.724 149.319,89.241 148.96,88.882 148.908,88.882 148.669,88.643 148.669,88.592 148.565,88.487 148.565,87.132 v1(148.986,86.711)
DDR_CH1_A1_D: U3.G14 U12.P2 | length 22.2
  Top Layer 1 _Signal w0.203: U3.G14@150.579,86.378 150.904,86.703 v1(150.904,86.726) ; v1(151.27,97.949) 151.307,97.986 151.307,98.102 151.554,98.349 U12.P2@151.554,98.389
  L3_Signals w0.179: v1(150.904,86.726) 151.242,87.064 151.242,87.788 151.2,87.831 151.2,88.141 151.212,88.153 151.212,89.327 151.025,89.515 151.025,90.698 151.144,90.818 151.144,92.001 151.025,92.121 151.025,92.43 151.2,92.605 151.2,93.585 151.2,93.675 150.767,93.675 150.767,93.88 151.615,93.88 151.615,94.084 150.767,94.084 150.767,94.289 151.48,94.289 151.48,94.494 150.767,94.494 150.767,94.699 151.338,94.699 151.338,94.903 150.767,94.903 150.767,95.108 151.501,95.108 151.501,95.313 150.767,95.313 150.767,95.518 151.615,95.518 151.615,95.722 150.767,95.722 150.767,95.927 151.615,95.927 151.615,96.132 151.016,96.132 151.016,96.336 151.2,96.336 151.2,96.491 ; 151.2,96.473 151.2,97.733 151.228,97.761 151.228,97.907 v1(151.27,97.949)
DDR_CH1_A2_C: U3.E13 U12.H9 | length 24
  Top Layer 1 _Signal w0.203: v1(147.434,103.612) 147.471,103.65 147.471,103.766 147.654,103.949 U12.H9@147.654,103.989 ; v1(149.556,88.037) 149.915,87.678 U3.E13@149.929,87.678
  Bottom Layer_Signals w0.203: v1(147.434,103.612) 147.444,103.603 147.974,103.603 148.607,104.235 148.741,104.235 148.937,104.04 149.256,104.04 149.451,104.235 149.612,104.235 149.616,104.231 149.717,104.129 150.587,104.129 150.587,103.901 149.891,103.901 149.891,103.672 150.587,103.672 150.587,103.444 149.891,103.444 149.891,103.215 150.176,103.215 150.176,102.986 149.891,102.986 149.891,102.871 149.891,102.681 149.648,102.438 149.648,97.393 149.371,97.116 149.371,91.001 149.686,90.687 149.686,89.408 150,89.094 150,88.482 v1(149.556,88.037)
DDR_CH1_A2_D: U3.G13 U12.R9 | length 20.4
  Top Layer 1 _Signal w0.203: U3.G13@149.929,86.378 149.929,86.41 150.227,86.707 v1(150.236,86.707) ; v1(151.851,103.636) U12.R9@152.204,103.989
  L3_Signals w0.179: v1(150.236,86.707) 150.761,87.233 150.761,90.807 150.881,90.927 150.881,91.888 150.759,92.01 150.759,92.465 150.415,92.809 150.415,93.836 150.415,93.926 149.971,93.926 149.971,94.131 150.44,94.131 150.44,94.335 150.241,94.335 150.241,94.54 150.415,94.54 150.415,94.977 150.415,98.489 150.876,98.951 150.876,99.841 151.095,100.06 151.4,100.06 151.505,100.165 151.505,103.29 v1(151.851,103.636)
DDR_CH1_A3_C: U3.D13 U12.H10 | length 19.4
  Top Layer 1 _Signal w0.203: U12.H10@147.654,104.789 147.654,104.756 147.969,104.442 v1(147.969,104.409) ; v1(149.615,88.665) 149.616,88.663 149.616,88.641 U3.D13@149.929,88.328
  L8_Signals w0.135: v1(147.969,104.409) 148.255,104.409 148.319,104.344 148.366,104.297 148.632,104.562 148.745,104.449 148.386,104.089 148.499,103.976 148.619,104.096 148.733,103.983 148.706,103.957 148.711,103.952 148.758,103.905 148.893,103.77 149.366,103.77 149.861,103.276 149.861,102.613 149.663,102.414 149.663,98.178 149.526,98.042 149.526,93.871 149.309,93.654 149.309,91.299 149.455,91.153 149.455,89.165 149.564,89.055 149.564,88.716 v1(149.615,88.665)
DDR_CH1_A3_D: U3.E14 U12.R10 | length 20.8
  Top Layer 1 _Signal w0.203: v1(149.881,104.519) 149.919,104.481 150.307,104.481 150.375,104.413 151.06,104.413 151.076,104.428 151.844,104.428 U12.R10@152.204,104.789 ; v1(150.248,87.344) 150.248,87.346 150.579,87.676 U3.E14@150.579,87.678
  L8_Signals w0.135: v1(149.881,104.519) 149.881,103.77 150.08,103.571 150.08,102.405 150.038,102.363 150.038,98.122 150.171,97.989 150.171,93.891 150.19,93.871 150.19,93.603 150.23,93.563 150.23,92.962 149.673,92.405 149.673,89.255 149.966,88.963 149.966,88.65 150.222,88.394 150.222,88.021 150.248,87.995 v1(150.248,87.344)
DDR_CH1_A4_C: U3.A10 U12.H11 | length 20.9
  Top Layer 1 _Signal w0.205: U12.H11@147.654,105.589 147.654,105.628 147.952,105.926 v1(147.952,105.974) ; U3.A10@147.979,90.278 147.979,90.309 147.722,90.567 147.722,91.264 147.694,91.291 147.694,92.688 150.152,95.145 150.152,97.347 150.078,97.42 150.078,101.131 150.117,101.17 150.117,101.407 149.506,102.018 149.506,102.105 149.506,102.208 149.338,102.208 149.338,102.438 150.017,102.438 150.017,102.669 149.338,102.669 149.338,102.9 149.51,102.9 v1(149.51,103.13) 149.506,103.13 149.506,103.378
  L3_Signals w0.179: v1(147.952,105.974) 149.017,105.974 149.471,105.519 149.471,103.169 v1(149.51,103.13)
DDR_CH1_A4_D: U3.A15 U12.R11 | length 19
  Top Layer 1 _Signal w0.203: v1(151.878,105.163) 151.915,105.201 151.915,105.26 152.204,105.549 U12.R11@152.204,105.589
  Top Layer 1 _Signal w0.205: U3.A15@151.229,90.278 151.711,90.76 151.711,92.042 151.784,92.115 151.784,92.464 151.711,92.537 v1(151.711,94.791)
  L8_Signals w0.135: v1(151.711,94.791) 151.711,97.067 151.181,97.597 151.124,97.597 150.918,97.803 150.918,97.86 150.515,98.263 150.515,99.83 150.515,99.898 150.475,99.898 150.475,100.058 151.272,100.058 151.272,100.218 150.475,100.218 150.475,100.379 150.765,100.379 150.765,100.539 150.515,100.539 150.515,100.644 150.515,102.222 150.517,102.224 150.517,103.802 151.373,104.658 151.47,104.658 151.676,104.864 151.676,104.889 151.878,105.091 v1(151.878,105.163)
DDR_CH1_A5_C: U3.B11 U12.J11 | length 19.6
  Top Layer 1 _Signal w0.203: U12.J11@148.304,105.589 148.304,105.549 148.518,105.336 148.518,105.236 v1(148.555,105.199) ; v1(148.341,89.893) 148.353,89.893 148.618,89.628 U3.B11@148.629,89.628
  L8_Signals w0.135: v1(148.341,89.893) 148.341,89.964 148.097,90.208 148.097,90.632 148.066,90.663 148.066,91.751 149.008,92.693 149.008,95.456 149.008,95.524 148.524,95.524 148.524,95.684 149.078,95.684 149.078,95.844 148.84,95.844 148.84,96.005 149.008,96.005 149.008,97.784 149.008,101.59 149.201,101.783 149.201,102.789 148.9,103.09 148.58,103.09 148.19,103.479 148.19,103.531 147.617,104.104 147.617,104.554 147.914,104.851 148.208,104.851 v1(148.555,105.199)
DDR_CH1_A5_D: U3.B14 U12.P11 | length 18.7
  Top Layer 1 _Signal w0.203: v1(150.285,89.354) 150.295,89.354 150.569,89.628 U3.B14@150.579,89.628 ; U12.P11@151.554,105.589 151.554,105.629 151.735,105.81 151.735,105.925 v1(151.773,105.963)
  L8_Signals w0.135: v1(150.285,89.354) 150.285,89.38 150.681,89.777 150.681,90.425 150.76,90.504 150.78,90.504 150.859,90.583 150.859,91.879 150.449,92.289 150.449,98.02 150.256,98.213 150.256,102.273 150.299,102.315 150.299,104.559 151.703,105.963 v1(151.773,105.963)
DDR_CH1_CLK_C_N: U3.A12 U12.J9 | length 21.9
  Top Layer 1 _Signal w0.161: U12.J9@148.304,103.989 148.304,103.938 148.541,103.701 v1(148.541,103.625) ; v1(148.945,91.702) 148.945,91.638 148.843,91.535 148.843,91.007 149.278,90.572 149.278,90.279 U3.A12@149.279,90.278
  Bottom Layer_Signals w0.161: v1(148.541,103.625) 148.541,103.583 149.329,102.796 149.329,102.544 149.382,102.49 149.382,97.503 149.105,97.226 149.105,96.548 148.526,95.969 148.526,95.858 148.526,95.62 149.105,95.62 149.105,95.433 148.526,95.433 148.526,95.246 149.105,95.246 149.105,95.06 148.526,95.06 148.526,94.873 149.105,94.873 149.105,94.686 148.526,94.686 148.526,94.5 149.105,94.5 149.105,94.313 148.526,94.313 148.526,94.126 149.105,94.126 149.105,93.939 148.526,93.939 148.526,93.753 149.105,93.753 149.105,93.566 148.526,93.566 148.526,93.299 148.526,92.186 148.945,91.767 v1(148.945,91.702)
DDR_CH1_CLK_C_P: U3.B12 U12.J8 | length 22.6
  Top Layer 1 _Signal w0.161: U12.J8@148.304,103.189 v1(148.849,102.644) ; v1(148.419,91.607) 148.419,91.543 148.518,91.443 148.518,90.873 148.954,90.437 148.954,89.982 149.279,89.656 U3.B12@149.279,89.628
  Bottom Layer_Signals w0.161: v1(148.419,91.607) 148.389,91.637 148.389,91.88 148.213,92.056 148.213,96.099 148.792,96.678 148.792,97.356 149.069,97.633 149.069,98.598 149.069,98.679 148.586,98.679 148.586,98.865 149.069,98.865 149.069,99.052 148.586,99.052 148.586,99.239 149.069,99.239 149.069,99.426 148.586,99.426 148.586,99.612 149.069,99.612 149.069,99.799 148.586,99.799 148.586,99.986 149.069,99.986 149.069,100.172 149.01,100.172 149.01,100.359 149.069,100.359 149.069,100.546 149.01,100.546 149.01,100.732 149.069,100.732 149.069,100.919 148.586,100.919 148.586,101.106 149.069,101.106 149.069,101.292 148.586,101.292 148.586,101.479 149.069,101.479 149.069,101.666 148.586,101.666 148.586,101.853 149.069,101.853 149.069,102.039 148.586,102.039 148.586,102.226 149.069,102.226 149.069,102.324 149.069,102.36 148.849,102.579 v1(148.849,102.644)
DDR_CH1_CLK_D_N: U3.A13 U12.P9 | length 20.8
  Top Layer 1 _Signal w0.161: U3.A13@149.929,90.278 149.93,90.279 149.93,90.547 150.099,90.715 150.099,91.404 150.07,91.433 150.07,91.572 v1(150.025,91.618) ; v1(151.18,103.573) 151.18,103.615 U12.P9@151.554,103.989
  Bottom Layer_Signals w0.161: v1(150.025,91.618) 150.025,91.683 150.114,91.772 150.114,92.086 150.114,92.167 149.759,92.167 149.759,92.354 150.114,92.354 150.114,92.54 149.759,92.54 149.759,92.727 150.114,92.727 150.114,93.04 150.114,93.137 150.243,93.267 150.243,93.704 150.066,93.882 149.985,93.963 149.637,93.963 149.637,94.154 149.914,94.154 149.914,94.346 149.637,94.346 149.637,94.538 149.914,94.538 149.914,94.73 149.637,94.73 149.637,94.922 149.914,94.922 149.914,95.113 149.637,95.113 149.637,95.305 149.914,95.305 149.914,95.497 149.637,95.497 149.637,95.689 149.914,95.689 149.914,95.88 149.637,95.88 149.637,96.072 149.914,96.072 149.914,96.264 149.637,96.264 149.637,96.456 149.914,96.456 149.914,96.647 149.637,96.647 149.637,96.839 149.914,96.839 149.914,97.031 149.855,97.031 149.855,97.223 149.914,97.223 149.914,98.357 149.914,102.328 150.837,103.25 150.891,103.25 151.18,103.54 v1(151.18,103.573)
DDR_CH1_CLK_D_P: U3.B13 U12.P8 | length 21.8
  Top Layer 1 _Signal w0.161: U3.B13@149.929,89.628 149.929,89.656 150.255,89.982 150.255,90.412 150.423,90.581 150.423,91.519 150.462,91.558 150.462,91.688 v1(150.508,91.733) ; v1(151.132,102.766) U12.P8@151.554,103.189
  Bottom Layer_Signals w0.161: v1(150.508,91.733) 150.462,91.779 150.462,91.912 150.427,91.947 150.427,91.993 150.427,92.26 150.747,92.26 150.747,92.447 150.427,92.447 150.427,92.634 150.747,92.634 150.747,92.82 150.427,92.82 150.427,93.007 150.747,93.007 150.747,93.194 150.557,93.194 150.557,93.38 150.747,93.38 150.747,93.567 150.557,93.567 150.557,93.834 150.336,94.055 150.228,94.163 150.228,101.337 150.228,101.451 150.36,101.583 150.691,101.253 150.823,101.385 150.228,101.979 150.36,102.111 150.955,101.517 151.087,101.649 150.383,102.353 150.515,102.485 151.219,101.781 151.351,101.913 150.647,102.617 150.813,102.783 150.984,102.783 151.115,102.783 v1(151.132,102.766)
DDR_CH1_DM0_C: U3.F8 U12.C3 | length 17.2
  Top Layer 1 _Signal w0.203: v1(143.979,98.789) 143.992,98.789 144.392,99.189 U12.C3@144.404,99.189 ; v1(146.357,87.35) U3.F8@146.679,87.028
  L8_Signals w0.135: v1(143.979,98.789) 143.974,98.789 143.9,98.715 143.9,98.383 143.212,97.695 143.212,97.625 142.881,97.294 142.881,97.003 143.024,96.86 143.024,95.907 143.676,95.255 143.676,92.953 143.775,92.854 143.823,92.806 144.682,91.947 144.913,92.178 145.026,92.065 144.426,91.464 144.539,91.351 145.006,91.818 145.119,91.705 144.652,91.238 144.766,91.124 145.024,91.383 145.119,91.287 145.119,91.192 145.119,89.615 146.357,88.378 v1(146.357,87.35)
DDR_CH1_DM0_D: U3.D20 U12.Y3 | length 12.7
  Top Layer 1 _Signal w0.205: U3.D20@154.479,88.328 154.488,88.328 154.779,88.037 v1(154.788,88.037) ; U12.Y3@155.454,99.189 155.454,99.15 155.731,98.873 155.731,98.762 v1(155.768,98.725)
  Bottom Layer_Signals w0.205: v1(154.788,88.037) 154.769,88.056 154.769,89.425 154.406,89.789 154.406,91.159 154.769,91.523 154.769,93.63 154.769,95.737 154.757,95.75 154.757,98.188 155.26,98.691 155.734,98.691 v1(155.768,98.725)
DDR_CH1_DM1_C: U3.D4 U12.C10 | length 26.4
  Top Layer 1 _Signal w0.203: U3.D4@144.079,88.328 144.088,88.328 144.088,88.332 144.372,88.616 v1(144.376,88.616) ; v1(144.117,104.439) 144.117,104.462 144.404,104.749 U12.C10@144.404,104.789
  Bottom Layer_Signals w0.203: v1(144.117,104.439) 142.321,104.439 142.036,104.154 142.005,104.154 141.779,103.928 141.779,103.897 140.968,103.086 140.968,101.502 140.968,98.266 140.16,97.458 139.892,97.458 139.166,96.731 139.166,96.118 139.084,96.037 139.084,95.717 139.31,95.492 139.971,95.492 140.068,95.589 140.968,95.589 140.968,95.202 141.019,95.202 141.019,94.973 140.605,94.973 140.605,94.744 141.203,94.744 141.203,94.516 140.605,94.516 140.605,94.287 141.203,94.287 141.203,94.059 140.791,94.059 140.791,93.83 140.903,93.83 140.903,93.728 140.903,91.623 142.948,89.577 142.948,89.507 143.839,88.616 v1(144.376,88.616)
DDR_CH1_DM1_D: U3.D22 U12.Y10 | length 23.8
  Top Layer 1 _Signal w0.203: U12.Y10@155.454,104.789 155.454,104.804 155.824,105.174 v1(155.824,105.19) ; U3.D22@155.779,88.328 155.811,88.328 156.127,88.644 v1(156.127,88.653)
  Bottom Layer_Signals w0.203: v1(155.824,105.19) 155.88,105.134 155.976,105.134 156.852,104.259 156.852,102.746 156.869,102.729 156.869,102.41 156.829,102.37 156.829,99.69 156.78,99.642 156.78,98.283 157.004,98.058 157.052,98.058 157.911,97.199 157.911,97.011 157.911,96.91 158.922,96.91 158.922,96.681 157.886,96.681 157.886,96.452 158.922,96.452 158.922,96.224 157.886,96.224 157.886,95.995 158.065,95.995 158.065,95.767 157.911,95.767 157.911,93.679 157.911,93.383 157.155,92.627 157.155,89.681 156.556,89.082 156.556,89.06 156.149,88.653 v1(156.127,88.653)
DDR_CH1_DQ0_C: U3.A8 U12.B2 | length 15.7
  Top Layer 1 _Signal w0.203: v1(142.555,95.5) 142.877,95.178 143.484,95.178 143.586,95.178 143.586,95.477 143.814,95.477 143.814,95.053 144.043,95.053 144.043,95.477 144.272,95.477 144.272,95.053 144.5,95.053 144.5,95.477 144.729,95.477 144.729,95.053 144.957,95.053 144.957,95.412 145.186,95.412 145.186,95.107 145.208,95.086 145.323,95.086 146.109,95.086 146.679,94.515 U3.A8@146.679,90.278 ; v1(142.805,98.025) 143.39,98.025 U12.B2@143.754,98.389
  L8_Signals w0.135: v1(142.555,95.5) 142.555,95.569 142.805,95.819 142.805,96.769 142.662,96.912 142.662,97.384 142.805,97.527 v1(142.805,98.025)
